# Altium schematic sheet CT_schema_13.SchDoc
size 144 x 119 mm
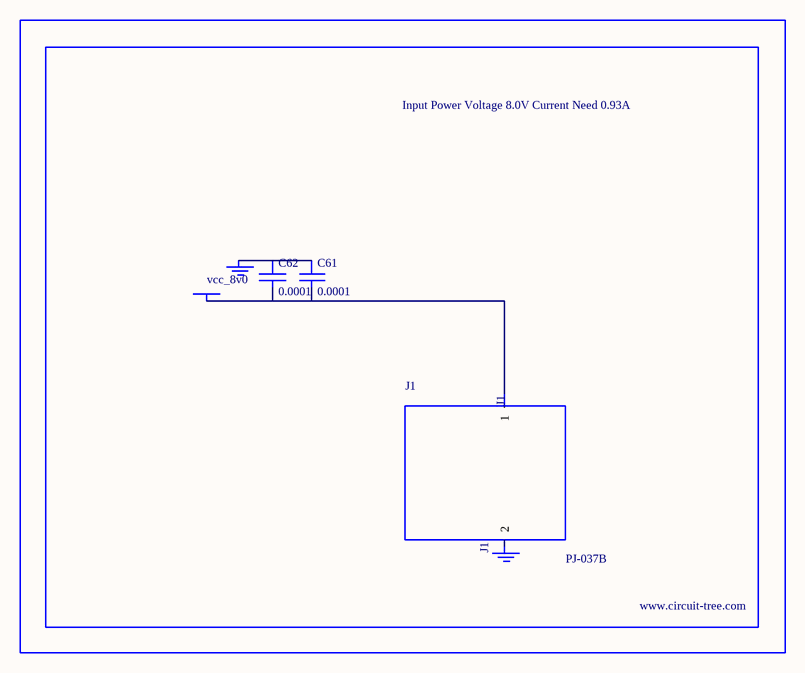
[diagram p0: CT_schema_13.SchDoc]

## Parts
BORDER12  (no value)
C61  0.0001  [EXV-9H]
C62  0.0001  [EXV-9H]
GND_INSTANCE_12_0  (no value)
GND_INSTANCE_12_1  (no value)
J1  PJ-037B  [PJ-037B_PACKAGE]
POWER_INSTANCE_12_0  vcc_8v0

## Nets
NetC61_1: C61.1 C62.1 GND_INSTANCE_12_0.0(GND)
NetC61_2: C61.2 C62.2 J1.1 POWER_INSTANCE_12_0.0(PWR)

Not connected (* = marked no-connect by the designer): GND_INSTANCE_12_1 0(GND); J1 2

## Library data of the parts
BORDER12 = BORDER_PAGE12
C61 C62 = EDK107M035A9HAA
GND_INSTANCE_12_0 GND_INSTANCE_12_1 = GND
POWER_INSTANCE_12_0 = PWR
